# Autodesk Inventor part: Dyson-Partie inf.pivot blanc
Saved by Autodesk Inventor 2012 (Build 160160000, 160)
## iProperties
Created: 2012-11
Part Number: Dyson-Partie inf.pivot blanc
Material: Default
Document SubType Name: Modeling
Designer: Administrateur
Density: 1 g/cm^3
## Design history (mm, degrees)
node "Dyson-Partie inf.pivot blanc1"
node "Dyson-Partie inf.pivot blanc"
node "Base1"
